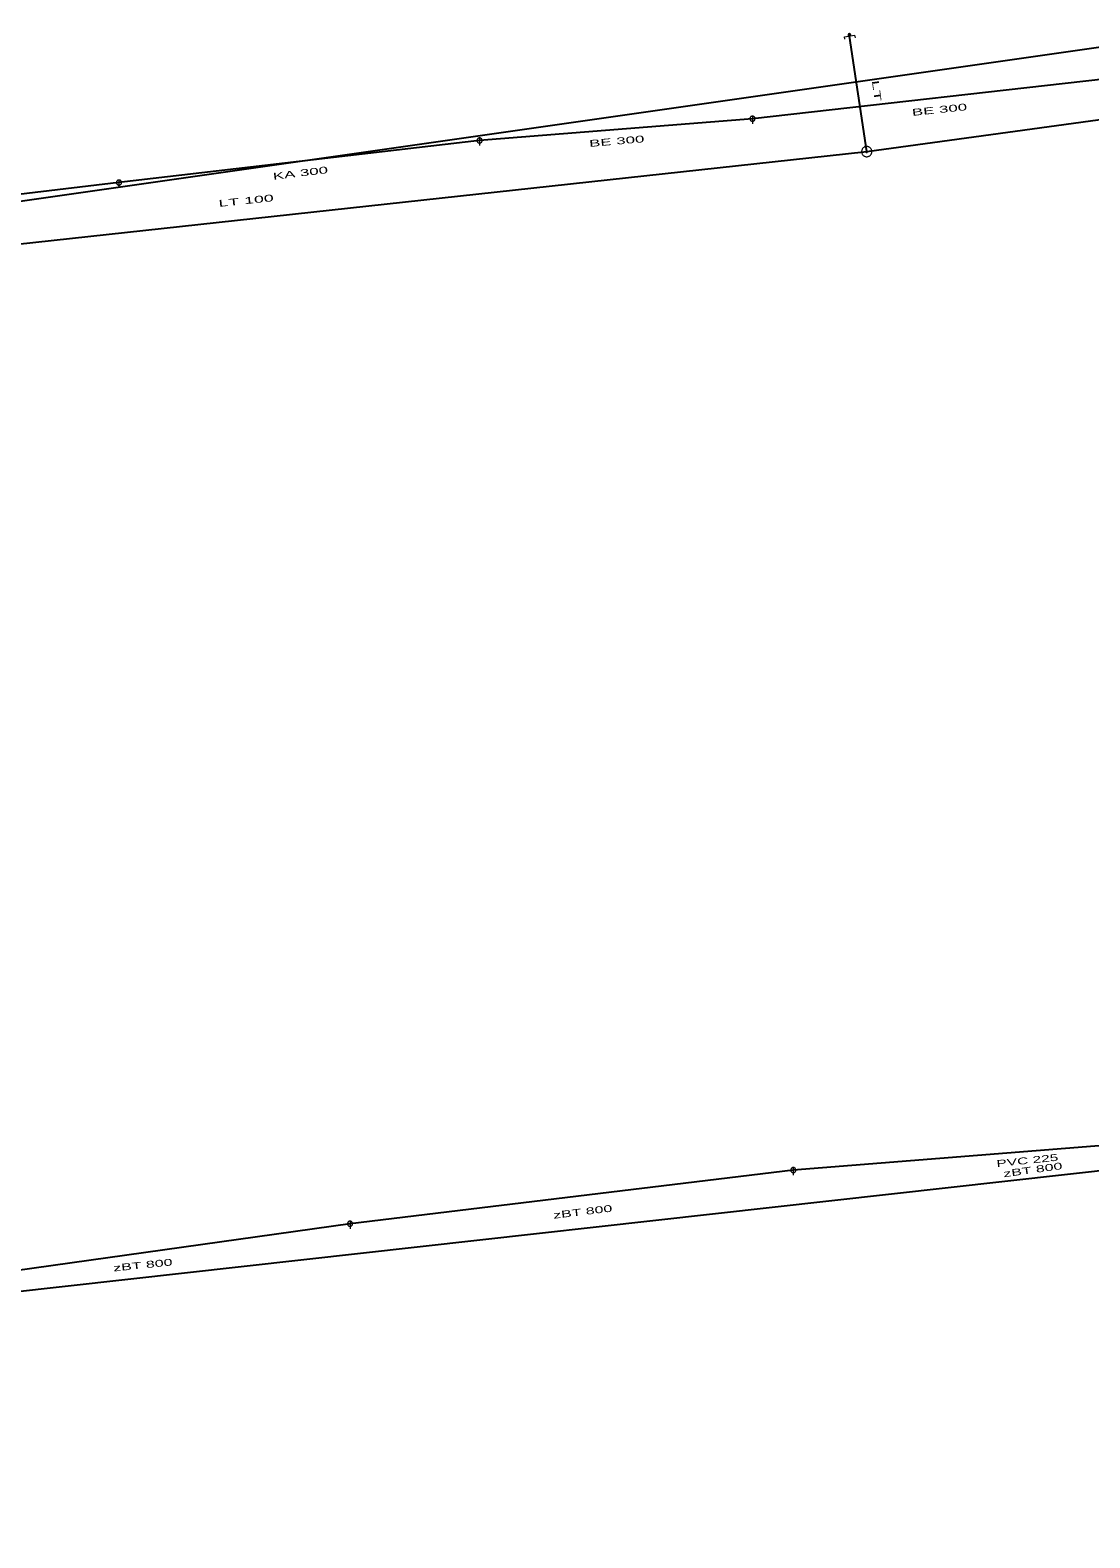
# Model space of a CAD drawing. Extents: x -687515 to -686506, y -974029 to -973461.
# Drawn here: x -687062.3 to -686958.8, y -973700.3 to -973553 of the extents above; entities that cross this region are included whole.
import ezdxf
from ezdxf.enums import TextEntityAlignment as Align

# ---------------------------------------------------------------- set-up
doc = ezdxf.new("R2010")
doc.units = 0
doc.header["$LTSCALE"] = 0.27
for name, color, linetype, lineweight in [('1', 7, 'Continuous', 13), ('14', 7, 'Continuous', 25), ('17', 7, 'Continuous', 25), ('22', 7, 'Continuous', 13), ('47', 7, 'Continuous', 13), ('9', 7, 'Continuous', 13)]:
    doc.layers.add(name, color=color, linetype=linetype, lineweight=lineweight)

msp = doc.modelspace()

# ---------------------------------------------------------------- linework, layer by layer
at = {"layer": '14', "lineweight": 13}
msp.add_line((-686982.238, -973553.58), (-686982.256, -973553.474), dxfattribs=at)
at = {"layer": '14'}
for p, q in [((-686955.417, -973557.554), (-686991.728, -973561.661)), ((-686991.728, -973561.661), (-687018.39, -973563.79)), ((-687018.39, -973563.79), (-687053.62, -973567.9)), ((-687053.62, -973567.9), (-687084.75, -973571.59)), ((-686944.599, -973660.967), (-686987.741, -973664.387)), ((-686987.741, -973664.387), (-687031.047, -973669.628)), ((-687031.047, -973669.628), (-687071.261, -973675.291))]:
    msp.add_line(p, q, dxfattribs=at)
at = {"layer": '17'}
for p, q in [((-686980.567, -973564.875), (-686982.238, -973553.58)), ((-687101.409, -973578.049), (-686980.567, -973564.875)), ((-686864.483, -973654.051), (-687064.409, -973676.368))]:
    msp.add_line(p, q, dxfattribs=at)
for points in [[(-686645.309, -973464.46), (-686646.34, -973464.75), (-686680.188, -973471.317), (-686771.188, -973470.317), (-686761.188, -973557.317), (-686894.188, -973571.317), (-686953.188, -973578.317), (-686955.188, -973554.317), (-687116.188, -973577.317), (-687229.188, -973601.317), (-687468.188, -973649.317), (-687458.188, -973700.317)], [(-686980.567, -973564.875), (-686956.331, -973561.544), (-686954.436, -973576.46), (-686865.945, -973565.93)]]:
    msp.add_lwpolyline(points, dxfattribs=at)
at = {"layer": '22'}
for p, q in [((-686991.727, -973561.409), (-686991.728, -973562.152)), ((-687018.389, -973563.538), (-687018.39, -973564.282)), ((-687053.619, -973567.648), (-687053.62, -973568.392)), ((-686987.74, -973664.135), (-686987.741, -973664.879)), ((-687031.046, -973669.376), (-687031.047, -973670.12))]:
    msp.add_line(p, q, dxfattribs=at)
for points in [[(-686991.476, -973561.661), (-686991.477, -973561.635), (-686991.481, -973561.609), (-686991.487, -973561.583), (-686991.497, -973561.559), (-686991.509, -973561.535), (-686991.523, -973561.513), (-686991.54, -973561.492), (-686991.558, -973561.474), (-686991.579, -973561.457), (-686991.601, -973561.443), (-686991.625, -973561.431), (-686991.649, -973561.421), (-686991.675, -973561.415), (-686991.701, -973561.411), (-686991.727, -973561.409), (-686991.753, -973561.41), (-686991.779, -973561.414), (-686991.805, -973561.42), (-686991.83, -973561.43), (-686991.853, -973561.442), (-686991.875, -973561.456), (-686991.896, -973561.473), (-686991.914, -973561.491), (-686991.931, -973561.512), (-686991.945, -973561.534), (-686991.957, -973561.558), (-686991.967, -973561.582), (-686991.974, -973561.608), (-686991.978, -973561.634), (-686991.98, -973561.66), (-686991.979, -973561.686), (-686991.975, -973561.712), (-686991.968, -973561.738), (-686991.958, -973561.763), (-686991.946, -973561.786), (-686991.932, -973561.808), (-686991.915, -973561.829), (-686991.897, -973561.847), (-686991.876, -973561.864), (-686991.854, -973561.878), (-686991.831, -973561.89), (-686991.806, -973561.9), (-686991.78, -973561.907), (-686991.754, -973561.911), (-686991.728, -973561.913), (-686991.702, -973561.912), (-686991.676, -973561.908), (-686991.65, -973561.901), (-686991.626, -973561.891), (-686991.602, -973561.879), (-686991.58, -973561.865), (-686991.559, -973561.848), (-686991.541, -973561.83), (-686991.524, -973561.809), (-686991.51, -973561.787), (-686991.498, -973561.764), (-686991.488, -973561.739), (-686991.482, -973561.713), (-686991.478, -973561.687)], [(-687018.138, -973563.79), (-687018.139, -973563.764), (-687018.143, -973563.738), (-687018.149, -973563.712), (-687018.159, -973563.688), (-687018.171, -973563.664), (-687018.185, -973563.642), (-687018.202, -973563.621), (-687018.22, -973563.603), (-687018.241, -973563.586), (-687018.263, -973563.572), (-687018.287, -973563.56), (-687018.311, -973563.55), (-687018.337, -973563.544), (-687018.363, -973563.54), (-687018.389, -973563.538), (-687018.415, -973563.539), (-687018.441, -973563.543), (-687018.467, -973563.549), (-687018.492, -973563.559), (-687018.515, -973563.571), (-687018.537, -973563.585), (-687018.558, -973563.602), (-687018.576, -973563.62), (-687018.593, -973563.641), (-687018.607, -973563.663), (-687018.619, -973563.687), (-687018.629, -973563.711), (-687018.636, -973563.737), (-687018.64, -973563.763), (-687018.642, -973563.789), (-687018.641, -973563.815), (-687018.637, -973563.841), (-687018.63, -973563.867), (-687018.62, -973563.892), (-687018.608, -973563.915), (-687018.594, -973563.937), (-687018.577, -973563.958), (-687018.559, -973563.976), (-687018.538, -973563.993), (-687018.516, -973564.007), (-687018.493, -973564.019), (-687018.468, -973564.029), (-687018.442, -973564.036), (-687018.416, -973564.04), (-687018.39, -973564.042), (-687018.364, -973564.041), (-687018.338, -973564.037), (-687018.312, -973564.03), (-687018.288, -973564.02), (-687018.264, -973564.008), (-687018.242, -973563.994), (-687018.221, -973563.977), (-687018.203, -973563.959), (-687018.186, -973563.938), (-687018.172, -973563.916), (-687018.16, -973563.893), (-687018.15, -973563.868), (-687018.144, -973563.842), (-687018.14, -973563.816)], [(-687053.368, -973567.9), (-687053.369, -973567.874), (-687053.373, -973567.848), (-687053.379, -973567.822), (-687053.389, -973567.798), (-687053.401, -973567.774), (-687053.415, -973567.752), (-687053.432, -973567.731), (-687053.45, -973567.713), (-687053.471, -973567.696), (-687053.493, -973567.682), (-687053.517, -973567.67), (-687053.541, -973567.66), (-687053.567, -973567.654), (-687053.593, -973567.65), (-687053.619, -973567.648), (-687053.645, -973567.649), (-687053.671, -973567.653), (-687053.697, -973567.659), (-687053.722, -973567.669), (-687053.745, -973567.681), (-687053.767, -973567.695), (-687053.788, -973567.712), (-687053.806, -973567.73), (-687053.823, -973567.751), (-687053.837, -973567.773), (-687053.849, -973567.797), (-687053.859, -973567.821), (-687053.866, -973567.847), (-687053.87, -973567.873), (-687053.872, -973567.899), (-687053.871, -973567.925), (-687053.867, -973567.951), (-687053.86, -973567.977), (-687053.85, -973568.002), (-687053.838, -973568.025), (-687053.824, -973568.047), (-687053.807, -973568.068), (-687053.789, -973568.086), (-687053.768, -973568.103), (-687053.746, -973568.117), (-687053.723, -973568.129), (-687053.698, -973568.139), (-687053.672, -973568.146), (-687053.646, -973568.15), (-687053.62, -973568.152), (-687053.594, -973568.151), (-687053.568, -973568.147), (-687053.542, -973568.14), (-687053.518, -973568.13), (-687053.494, -973568.118), (-687053.472, -973568.104), (-687053.451, -973568.087), (-687053.433, -973568.069), (-687053.416, -973568.048), (-687053.402, -973568.026), (-687053.39, -973568.003), (-687053.38, -973567.978), (-687053.374, -973567.952), (-687053.37, -973567.926)], [(-686987.489, -973664.387), (-686987.49, -973664.361), (-686987.494, -973664.335), (-686987.5, -973664.309), (-686987.51, -973664.285), (-686987.522, -973664.261), (-686987.536, -973664.239), (-686987.553, -973664.218), (-686987.571, -973664.2), (-686987.592, -973664.183), (-686987.614, -973664.169), (-686987.638, -973664.157), (-686987.662, -973664.147), (-686987.688, -973664.141), (-686987.714, -973664.137), (-686987.74, -973664.135), (-686987.766, -973664.136), (-686987.792, -973664.14), (-686987.818, -973664.146), (-686987.843, -973664.156), (-686987.866, -973664.168), (-686987.888, -973664.182), (-686987.909, -973664.199), (-686987.927, -973664.217), (-686987.944, -973664.238), (-686987.958, -973664.26), (-686987.97, -973664.284), (-686987.98, -973664.308), (-686987.987, -973664.334), (-686987.991, -973664.36), (-686987.993, -973664.386), (-686987.992, -973664.412), (-686987.988, -973664.438), (-686987.981, -973664.464), (-686987.971, -973664.489), (-686987.959, -973664.512), (-686987.945, -973664.534), (-686987.928, -973664.555), (-686987.91, -973664.573), (-686987.889, -973664.59), (-686987.867, -973664.604), (-686987.844, -973664.616), (-686987.819, -973664.626), (-686987.793, -973664.633), (-686987.767, -973664.637), (-686987.741, -973664.639), (-686987.715, -973664.638), (-686987.689, -973664.634), (-686987.663, -973664.627), (-686987.639, -973664.617), (-686987.615, -973664.605), (-686987.593, -973664.591), (-686987.572, -973664.574), (-686987.554, -973664.556), (-686987.537, -973664.535), (-686987.523, -973664.513), (-686987.511, -973664.49), (-686987.501, -973664.465), (-686987.495, -973664.439), (-686987.491, -973664.413)], [(-687030.795, -973669.628), (-687030.796, -973669.602), (-687030.8, -973669.576), (-687030.806, -973669.55), (-687030.816, -973669.526), (-687030.828, -973669.502), (-687030.842, -973669.48), (-687030.859, -973669.459), (-687030.877, -973669.441), (-687030.898, -973669.424), (-687030.92, -973669.41), (-687030.944, -973669.398), (-687030.968, -973669.388), (-687030.994, -973669.382), (-687031.02, -973669.378), (-687031.046, -973669.376), (-687031.072, -973669.377), (-687031.098, -973669.381), (-687031.124, -973669.387), (-687031.149, -973669.397), (-687031.172, -973669.409), (-687031.194, -973669.423), (-687031.215, -973669.44), (-687031.233, -973669.458), (-687031.25, -973669.479), (-687031.264, -973669.501), (-687031.276, -973669.525), (-687031.286, -973669.549), (-687031.293, -973669.575), (-687031.297, -973669.601), (-687031.299, -973669.627), (-687031.298, -973669.653), (-687031.294, -973669.679), (-687031.287, -973669.705), (-687031.277, -973669.73), (-687031.265, -973669.753), (-687031.251, -973669.775), (-687031.234, -973669.796), (-687031.216, -973669.814), (-687031.195, -973669.831), (-687031.173, -973669.845), (-687031.15, -973669.857), (-687031.125, -973669.867), (-687031.099, -973669.874), (-687031.073, -973669.878), (-687031.047, -973669.88), (-687031.021, -973669.879), (-687030.995, -973669.875), (-687030.969, -973669.868), (-687030.945, -973669.858), (-687030.921, -973669.846), (-687030.899, -973669.832), (-687030.878, -973669.815), (-687030.86, -973669.797), (-687030.843, -973669.776), (-687030.829, -973669.754), (-687030.817, -973669.731), (-687030.807, -973669.706), (-687030.801, -973669.68), (-687030.797, -973669.654)]]:
    msp.add_lwpolyline(points, close=True, dxfattribs=at)
at = {"layer": '47'}
msp.add_lwpolyline([(-686982.691, -973553.901), (-686982.728, -973553.652), (-686981.747, -973553.507), (-686981.71, -973553.756)], dxfattribs=at)
for points in [[(-686980.067, -973564.875), (-686980.07, -973564.823), (-686980.078, -973564.771), (-686980.092, -973564.721), (-686980.11, -973564.672), (-686980.134, -973564.625), (-686980.163, -973564.581), (-686980.196, -973564.541), (-686980.233, -973564.504), (-686980.273, -973564.471), (-686980.317, -973564.442), (-686980.364, -973564.418), (-686980.413, -973564.4), (-686980.463, -973564.386), (-686980.515, -973564.378), (-686980.567, -973564.375), (-686980.619, -973564.378), (-686980.671, -973564.386), (-686980.722, -973564.4), (-686980.77, -973564.418), (-686980.817, -973564.442), (-686980.861, -973564.471), (-686980.902, -973564.504), (-686980.939, -973564.541), (-686980.972, -973564.581), (-686981, -973564.625), (-686981.024, -973564.672), (-686981.043, -973564.721), (-686981.056, -973564.771), (-686981.064, -973564.823), (-686981.067, -973564.875), (-686981.064, -973564.927), (-686981.056, -973564.979), (-686981.043, -973565.03), (-686981.024, -973565.078), (-686981, -973565.125), (-686980.972, -973565.169), (-686980.939, -973565.21), (-686980.902, -973565.247), (-686980.861, -973565.28), (-686980.817, -973565.308), (-686980.77, -973565.332), (-686980.722, -973565.351), (-686980.671, -973565.364), (-686980.619, -973565.372), (-686980.567, -973565.375), (-686980.515, -973565.372), (-686980.463, -973565.364), (-686980.413, -973565.351), (-686980.364, -973565.332), (-686980.317, -973565.308), (-686980.273, -973565.28), (-686980.233, -973565.247), (-686980.196, -973565.21), (-686980.163, -973565.169), (-686980.134, -973565.125), (-686980.11, -973565.078), (-686980.092, -973565.03), (-686980.078, -973564.979), (-686980.07, -973564.927)], [(-686980.485, -973564.875), (-686980.485, -973564.866), (-686980.487, -973564.858), (-686980.489, -973564.85), (-686980.492, -973564.842), (-686980.496, -973564.834), (-686980.501, -973564.827), (-686980.506, -973564.82), (-686980.512, -973564.814), (-686980.519, -973564.809), (-686980.526, -973564.804), (-686980.534, -973564.8), (-686980.542, -973564.797), (-686980.55, -973564.795), (-686980.558, -973564.793), (-686980.567, -973564.793), (-686980.576, -973564.793), (-686980.584, -973564.795), (-686980.592, -973564.797), (-686980.6, -973564.8), (-686980.608, -973564.804), (-686980.615, -973564.809), (-686980.622, -973564.814), (-686980.628, -973564.82), (-686980.634, -973564.827), (-686980.638, -973564.834), (-686980.642, -973564.842), (-686980.645, -973564.85), (-686980.647, -973564.858), (-686980.649, -973564.866), (-686980.649, -973564.875), (-686980.649, -973564.884), (-686980.647, -973564.892), (-686980.645, -973564.9), (-686980.642, -973564.908), (-686980.638, -973564.916), (-686980.634, -973564.923), (-686980.628, -973564.93), (-686980.622, -973564.936), (-686980.615, -973564.942), (-686980.608, -973564.946), (-686980.6, -973564.95), (-686980.592, -973564.953), (-686980.584, -973564.955), (-686980.576, -973564.957), (-686980.567, -973564.957), (-686980.558, -973564.957), (-686980.55, -973564.955), (-686980.542, -973564.953), (-686980.534, -973564.95), (-686980.526, -973564.946), (-686980.519, -973564.942), (-686980.512, -973564.936), (-686980.506, -973564.93), (-686980.501, -973564.923), (-686980.496, -973564.916), (-686980.492, -973564.908), (-686980.489, -973564.9), (-686980.487, -973564.892), (-686980.485, -973564.884)]]:
    msp.add_lwpolyline(points, close=True, dxfattribs=at)
at = {"layer": '9'}
for points in [[(-686982.13, -973553.474), (-686982.131, -973553.461), (-686982.133, -973553.448), (-686982.136, -973553.435), (-686982.141, -973553.423), (-686982.147, -973553.411), (-686982.154, -973553.4), (-686982.162, -973553.39), (-686982.172, -973553.38), (-686982.182, -973553.372), (-686982.193, -973553.365), (-686982.205, -973553.359), (-686982.217, -973553.354), (-686982.23, -973553.351), (-686982.243, -973553.349), (-686982.256, -973553.348), (-686982.269, -973553.349), (-686982.282, -973553.351), (-686982.295, -973553.354), (-686982.307, -973553.359), (-686982.319, -973553.365), (-686982.33, -973553.372), (-686982.34, -973553.38), (-686982.35, -973553.39), (-686982.358, -973553.4), (-686982.365, -973553.411), (-686982.371, -973553.423), (-686982.376, -973553.435), (-686982.379, -973553.448), (-686982.381, -973553.461), (-686982.382, -973553.474), (-686982.381, -973553.487), (-686982.379, -973553.5), (-686982.376, -973553.513), (-686982.371, -973553.525), (-686982.365, -973553.537), (-686982.358, -973553.548), (-686982.35, -973553.558), (-686982.34, -973553.568), (-686982.33, -973553.576), (-686982.319, -973553.583), (-686982.307, -973553.589), (-686982.295, -973553.594), (-686982.282, -973553.597), (-686982.269, -973553.599), (-686982.256, -973553.6), (-686982.243, -973553.599), (-686982.23, -973553.597), (-686982.217, -973553.594), (-686982.205, -973553.589), (-686982.193, -973553.583), (-686982.182, -973553.576), (-686982.172, -973553.568), (-686982.162, -973553.558), (-686982.154, -973553.548), (-686982.147, -973553.537), (-686982.141, -973553.525), (-686982.136, -973553.513), (-686982.133, -973553.5), (-686982.131, -973553.487)], [(-686982.15, -973553.474), (-686982.15, -973553.463), (-686982.152, -973553.452), (-686982.155, -973553.441), (-686982.159, -973553.431), (-686982.164, -973553.421), (-686982.17, -973553.412), (-686982.177, -973553.403), (-686982.185, -973553.395), (-686982.194, -973553.388), (-686982.203, -973553.382), (-686982.213, -973553.377), (-686982.223, -973553.373), (-686982.234, -973553.37), (-686982.245, -973553.368), (-686982.256, -973553.368), (-686982.267, -973553.368), (-686982.278, -973553.37), (-686982.289, -973553.373), (-686982.299, -973553.377), (-686982.309, -973553.382), (-686982.318, -973553.388), (-686982.327, -973553.395), (-686982.335, -973553.403), (-686982.342, -973553.412), (-686982.348, -973553.421), (-686982.353, -973553.431), (-686982.357, -973553.441), (-686982.36, -973553.452), (-686982.362, -973553.463), (-686982.362, -973553.474), (-686982.362, -973553.485), (-686982.36, -973553.496), (-686982.357, -973553.507), (-686982.353, -973553.517), (-686982.348, -973553.527), (-686982.342, -973553.536), (-686982.335, -973553.545), (-686982.327, -973553.553), (-686982.318, -973553.56), (-686982.309, -973553.566), (-686982.299, -973553.571), (-686982.289, -973553.575), (-686982.278, -973553.578), (-686982.267, -973553.58), (-686982.256, -973553.58), (-686982.245, -973553.58), (-686982.234, -973553.578), (-686982.223, -973553.575), (-686982.213, -973553.571), (-686982.203, -973553.566), (-686982.194, -973553.56), (-686982.185, -973553.553), (-686982.177, -973553.545), (-686982.17, -973553.536), (-686982.164, -973553.527), (-686982.159, -973553.517), (-686982.155, -973553.507), (-686982.152, -973553.496), (-686982.15, -973553.485)], [(-686982.169, -973553.474), (-686982.17, -973553.465), (-686982.171, -973553.456), (-686982.174, -973553.447), (-686982.177, -973553.439), (-686982.181, -973553.431), (-686982.186, -973553.423), (-686982.192, -973553.416), (-686982.198, -973553.41), (-686982.205, -973553.404), (-686982.213, -973553.399), (-686982.221, -973553.395), (-686982.229, -973553.392), (-686982.238, -973553.389), (-686982.247, -973553.388), (-686982.256, -973553.387), (-686982.265, -973553.388), (-686982.274, -973553.389), (-686982.283, -973553.392), (-686982.291, -973553.395), (-686982.299, -973553.399), (-686982.307, -973553.404), (-686982.314, -973553.41), (-686982.32, -973553.416), (-686982.326, -973553.423), (-686982.331, -973553.431), (-686982.335, -973553.439), (-686982.338, -973553.447), (-686982.341, -973553.456), (-686982.342, -973553.465), (-686982.343, -973553.474), (-686982.342, -973553.483), (-686982.341, -973553.492), (-686982.338, -973553.501), (-686982.335, -973553.509), (-686982.331, -973553.517), (-686982.326, -973553.525), (-686982.32, -973553.532), (-686982.314, -973553.538), (-686982.307, -973553.544), (-686982.299, -973553.549), (-686982.291, -973553.553), (-686982.283, -973553.556), (-686982.274, -973553.559), (-686982.265, -973553.56), (-686982.256, -973553.561), (-686982.247, -973553.56), (-686982.238, -973553.559), (-686982.229, -973553.556), (-686982.221, -973553.553), (-686982.213, -973553.549), (-686982.205, -973553.544), (-686982.198, -973553.538), (-686982.192, -973553.532), (-686982.186, -973553.525), (-686982.181, -973553.517), (-686982.177, -973553.509), (-686982.174, -973553.501), (-686982.171, -973553.492), (-686982.17, -973553.483)], [(-686982.189, -973553.474), (-686982.189, -973553.467), (-686982.191, -973553.46), (-686982.192, -973553.453), (-686982.195, -973553.447), (-686982.198, -973553.441), (-686982.202, -973553.435), (-686982.206, -973553.429), (-686982.211, -973553.424), (-686982.217, -973553.42), (-686982.223, -973553.416), (-686982.229, -973553.413), (-686982.235, -973553.41), (-686982.242, -973553.409), (-686982.249, -973553.407), (-686982.256, -973553.407), (-686982.263, -973553.407), (-686982.27, -973553.409), (-686982.277, -973553.41), (-686982.283, -973553.413), (-686982.29, -973553.416), (-686982.295, -973553.42), (-686982.301, -973553.424), (-686982.306, -973553.429), (-686982.31, -973553.435), (-686982.314, -973553.441), (-686982.317, -973553.447), (-686982.32, -973553.453), (-686982.322, -973553.46), (-686982.323, -973553.467), (-686982.323, -973553.474), (-686982.323, -973553.481), (-686982.322, -973553.488), (-686982.32, -973553.495), (-686982.317, -973553.501), (-686982.314, -973553.508), (-686982.31, -973553.513), (-686982.306, -973553.519), (-686982.301, -973553.524), (-686982.295, -973553.528), (-686982.29, -973553.532), (-686982.283, -973553.535), (-686982.277, -973553.538), (-686982.27, -973553.54), (-686982.263, -973553.541), (-686982.256, -973553.541), (-686982.249, -973553.541), (-686982.242, -973553.54), (-686982.235, -973553.538), (-686982.229, -973553.535), (-686982.223, -973553.532), (-686982.217, -973553.528), (-686982.211, -973553.524), (-686982.206, -973553.519), (-686982.202, -973553.513), (-686982.198, -973553.508), (-686982.195, -973553.501), (-686982.192, -973553.495), (-686982.191, -973553.488), (-686982.189, -973553.481)], [(-686982.209, -973553.474), (-686982.209, -973553.469), (-686982.21, -973553.464), (-686982.211, -973553.459), (-686982.213, -973553.455), (-686982.215, -973553.45), (-686982.218, -973553.446), (-686982.221, -973553.443), (-686982.225, -973553.439), (-686982.228, -973553.436), (-686982.232, -973553.433), (-686982.237, -973553.431), (-686982.241, -973553.429), (-686982.246, -973553.428), (-686982.251, -973553.427), (-686982.256, -973553.427), (-686982.261, -973553.427), (-686982.266, -973553.428), (-686982.271, -973553.429), (-686982.275, -973553.431), (-686982.28, -973553.433), (-686982.284, -973553.436), (-686982.288, -973553.439), (-686982.291, -973553.443), (-686982.294, -973553.446), (-686982.297, -973553.45), (-686982.299, -973553.455), (-686982.301, -973553.459), (-686982.302, -973553.464), (-686982.303, -973553.469), (-686982.303, -973553.474), (-686982.303, -973553.479), (-686982.302, -973553.484), (-686982.301, -973553.489), (-686982.299, -973553.493), (-686982.297, -973553.498), (-686982.294, -973553.502), (-686982.291, -973553.506), (-686982.288, -973553.509), (-686982.284, -973553.512), (-686982.28, -973553.515), (-686982.275, -973553.517), (-686982.271, -973553.519), (-686982.266, -973553.52), (-686982.261, -973553.521), (-686982.256, -973553.521), (-686982.251, -973553.521), (-686982.246, -973553.52), (-686982.241, -973553.519), (-686982.237, -973553.517), (-686982.232, -973553.515), (-686982.228, -973553.512), (-686982.225, -973553.509), (-686982.221, -973553.506), (-686982.218, -973553.502), (-686982.215, -973553.498), (-686982.213, -973553.493), (-686982.211, -973553.489), (-686982.21, -973553.484), (-686982.209, -973553.479)], [(-686982.229, -973553.474), (-686982.229, -973553.471), (-686982.229, -973553.468), (-686982.23, -973553.466), (-686982.231, -973553.463), (-686982.232, -973553.46), (-686982.234, -973553.458), (-686982.236, -973553.456), (-686982.238, -973553.454), (-686982.24, -973553.452), (-686982.242, -973553.45), (-686982.245, -973553.449), (-686982.248, -973553.448), (-686982.25, -973553.447), (-686982.253, -973553.447), (-686982.256, -973553.447), (-686982.259, -973553.447), (-686982.262, -973553.447), (-686982.265, -973553.448), (-686982.267, -973553.449), (-686982.27, -973553.45), (-686982.272, -973553.452), (-686982.275, -973553.454), (-686982.277, -973553.456), (-686982.278, -973553.458), (-686982.28, -973553.46), (-686982.281, -973553.463), (-686982.282, -973553.466), (-686982.283, -973553.468), (-686982.283, -973553.471), (-686982.284, -973553.474), (-686982.283, -973553.477), (-686982.283, -973553.48), (-686982.282, -973553.483), (-686982.281, -973553.485), (-686982.28, -973553.488), (-686982.278, -973553.49), (-686982.277, -973553.493), (-686982.275, -973553.495), (-686982.272, -973553.496), (-686982.27, -973553.498), (-686982.267, -973553.499), (-686982.265, -973553.5), (-686982.262, -973553.501), (-686982.259, -973553.501), (-686982.256, -973553.502), (-686982.253, -973553.501), (-686982.25, -973553.501), (-686982.248, -973553.5), (-686982.245, -973553.499), (-686982.242, -973553.498), (-686982.24, -973553.496), (-686982.238, -973553.495), (-686982.236, -973553.493), (-686982.234, -973553.49), (-686982.232, -973553.488), (-686982.231, -973553.485), (-686982.23, -973553.483), (-686982.229, -973553.48), (-686982.229, -973553.477)], [(-686982.248, -973553.474), (-686982.248, -973553.473), (-686982.248, -973553.472), (-686982.249, -973553.472), (-686982.249, -973553.471), (-686982.249, -973553.47), (-686982.25, -973553.469), (-686982.25, -973553.469), (-686982.251, -973553.468), (-686982.251, -973553.468), (-686982.252, -973553.467), (-686982.253, -973553.467), (-686982.254, -973553.467), (-686982.254, -973553.466), (-686982.255, -973553.466), (-686982.256, -973553.466), (-686982.257, -973553.466), (-686982.258, -973553.466), (-686982.258, -973553.467), (-686982.259, -973553.467), (-686982.26, -973553.467), (-686982.261, -973553.468), (-686982.261, -973553.468), (-686982.262, -973553.469), (-686982.262, -973553.469), (-686982.263, -973553.47), (-686982.263, -973553.471), (-686982.264, -973553.472), (-686982.264, -973553.472), (-686982.264, -973553.473), (-686982.264, -973553.474), (-686982.264, -973553.475), (-686982.264, -973553.476), (-686982.264, -973553.476), (-686982.263, -973553.477), (-686982.263, -973553.478), (-686982.262, -973553.479), (-686982.262, -973553.479), (-686982.261, -973553.48), (-686982.261, -973553.48), (-686982.26, -973553.481), (-686982.259, -973553.481), (-686982.258, -973553.482), (-686982.258, -973553.482), (-686982.257, -973553.482), (-686982.256, -973553.482), (-686982.255, -973553.482), (-686982.254, -973553.482), (-686982.254, -973553.482), (-686982.253, -973553.481), (-686982.252, -973553.481), (-686982.251, -973553.48), (-686982.251, -973553.48), (-686982.25, -973553.479), (-686982.25, -973553.479), (-686982.249, -973553.478), (-686982.249, -973553.477), (-686982.249, -973553.476), (-686982.248, -973553.476), (-686982.248, -973553.475)]]:
    msp.add_lwpolyline(points, close=True, dxfattribs=at)

# ---------------------------------------------------------------- texts
at = {"layer": '1'}
for s, rotation, width, p in [('LT', 278, 2, (-686979.919, -973558.976)), ('BE 300', 6, 1.85, (-686973.422, -973561.103)), ('BE 300', 5, 1.85, (-687004.96, -973564.185)), ('KA 300', 7, 1.85, (-687035.854, -973567.301)), ('LT 100', 6, 1.95, (-687041.167, -973569.993)), ('PVC 225 ', 6, 1.7, (-686964.626, -973663.752)), ('zBT 800 ', 8, 1.75, (-686964.077, -973664.654)), ('zBT 800 ', 7, 1.75, (-687008.061, -973668.76)), ('zBT 800 ', 6, 1.75, (-687051.041, -973673.971))]:
    msp.add_text(s, height=0.6667, rotation=rotation, dxfattribs=dict(at, width=width)).set_placement(p, align=Align.CENTER)

doc.saveas('drawing.dxf')
